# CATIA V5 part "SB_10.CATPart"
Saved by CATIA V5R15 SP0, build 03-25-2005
Part number: SB_10
Material "Bordeaux Red": density 7860 kg/m3, Young's modulus 2e+11 Pa, Poisson ratio 0.266
Bounding box of the stored display mesh (mm): x 0 to 79, y 0 to 790, z 0 to 49.2
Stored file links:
  E:\#01 CATIA Lecture Materials\#06 DMU\#11 DMU Page01 KIN EX11\SB_10.CATPart
  C:\Program Files\Dassault Systemes\B20\win_b64\startup\materials\Catalog.CATMaterial
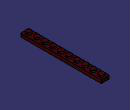
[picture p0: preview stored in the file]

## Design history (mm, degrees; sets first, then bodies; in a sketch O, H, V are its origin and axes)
Body1 (main body), material "Bordeaux Red"
  Sketch1 on xy-plane, origin (0, 0, 0), H (1, 0, 0), V (0, 1, 0)
    circle A1 centre (39.5, 39.5) radius 24.5
    point P1 (39.5, 39.5)
    radius A1 = 24.5
    distance P1 H = 39.5
    distance P1 V = 39.5
  Pad1: profile Sketch1, direction (0, 0, 1), length 49.2
  RectPattern1: of Pad1, direction 1 instances 10, spacing 79, along yz-plane
  Sketch2 on xy-plane, origin (0, 0, 0), H (1, 0, 0), V (0, 1, 0)
    point P1 (0, 790)
    line L1 (0, 790) -> (79, 790)
    line L2 (79, 790) -> (79, 0)
    line L3 (79, 0) -> (0, 0)
    line L4 (0, 0) -> (0, 790)
    point P3 (79, 0)
    distance L2 L4 = 79
    distance L1 L3 = 790 {= RectPattern1.Nb1 * 79mm}
    coincidence: P1 V, P3 H
    horizontal: L1 H, L3 H
    vertical: L2 V, L4 V
  Pad2: profile Sketch2, direction (0, 0, 1), length 32
  Shell1: ExtOffset 0, Face face of Pad2, IntOffset 15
